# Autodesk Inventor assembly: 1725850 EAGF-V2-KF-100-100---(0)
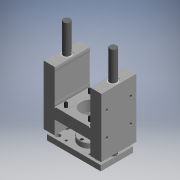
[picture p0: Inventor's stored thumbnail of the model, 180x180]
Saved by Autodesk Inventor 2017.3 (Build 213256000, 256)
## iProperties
Category: PARTsolutions
Company: FESTO
Part Number: 1725850 EAGF-V2-KF-100-100---(0)
Catalog Web Link: www.cadenas.de
Description: EAGF-guide unit
Vendor: FESTO
Document SubType Name: Assembly
Designer: partserver
Manufacturer: FESTO
Mass: 14023 g
Surface Area: 4822.3 cm^2
Volume: 3416.6 cm^3
Density: 4.10438 g/cm^3
Title: 1725850 EAGF-V2-KF-100-100
Author: Cadenas PARTsolutions
Comments: guide unit
PSOL_IDENT_0: {ATYP=ASSISTANT},{DATA=script=$CADENAS_DATA/23d-libs/festo/webfesto.vbb&M_FAMILY=EAGF&M_GROUP=01&M_P
PSOL_IDENT_1: ARTNO=1725850&IDCODE1=EAGF-V2-KF-100-100&IDCODE2=&customer_number_cns=&MATES=1&LOD=HI&LOCKERP=0&SING
PSOL_IDENT_2: LEPART=1}
NB: 1725850 EAGF-V2-KF-100-100---(0)
NN: EAGF
NT: guide unit
NBSYN: $TNR. $TYP.---($HUBST.)
LINA: 1725850 EAGF-V2-KF-100-100
CATALOG: Festo
TNR: 1725850
TYP: EAGF-V2-KF-100-100
HUBST: 0
L1: 362.8
L2: 126.6
L3: 220
L4: 40
L5: 128
L6: 20
L7: 24.5
L8: 89
L9: 0
L10: 15
L11: 39
H1: 213
H2: 200
H3: 89
H4: 150
H5: 131
H6: 172
H7: 150
B1: 130
B2: 120
B3: 89
B4: 89
B5: 89
D1: 87
D2: 25
D3: 18
D4: 11
D5: 70
KK: M20x1.5
G1: M18
G2: M10
G3: M10
T1: 20
T2: 11
SW: 27
CNSMASSEXACT: 14.023
SUPPLIER: FESTO
ARTICLENO: 1725850 EAGF-V2-KF-100-100---(0)
BOMINFO: 1725850 EAGF-V2-KF-100-100
CREATOR: CADENAS GmbH
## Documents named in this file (12)
- e:\temp\worker_18\temp\exporttempdir_1120_80_rasIC\format_0\1725850 EAGF-V2-KF-100-100---(0).iam
- e:\temp\worker_18\temp\exporttempdir_1120_80_rasIC\format_0\2608532 EAGF-V2-KF-100---(F).ipt
- e:\temp\worker_18\temp\exporttempdir_1120_80_rasIC\format_0\247465 FEN-80-SD---(SD).ipt
- e:\temp\worker_18\temp\exporttempdir_1120_80_rasIC\format_0\242770 EAGF 25x35x40---(B).ipt
- e:\temp\worker_18\temp\exporttempdir_1120_80_rasIC\format_0\1558863 EAGF-V2-KF-100---(J).ipt
- e:\temp\worker_18\temp\exporttempdir_1120_80_rasIC\format_0\1559396 EAGF-V2-KF-100---(R).ipt
- e:\temp\worker_18\temp\exporttempdir_1120_80_rasIC\format_0\1559400 EAGF-V2-KF-80_100---(GS).ipt
- e:\temp\worker_18\temp\exporttempdir_1120_80_rasIC\format_0\DIN-913 - M18x20.ipt
- e:\temp\worker_18\temp\exporttempdir_1120_80_rasIC\format_0\2608532 EAGF-100-100-KF---(FST).ipt
- e:\temp\worker_18\temp\exporttempdir_1120_80_rasIC\format_0\DIN-912 - M12x25(F).ipt
- e:\temp\worker_18\temp\exporttempdir_1120_80_rasIC\format_0\DIN-6912 - M12x25(F).ipt
- e:\temp\worker_18\temp\exporttempdir_1120_80_rasIC\format_0\DIN-912 - M10x50(F).ipt
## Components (25 placed, 11 different names)
1. 2608532 EAGF-V2-KF-100---(F):1 — ABSTREIF_V_1_XY@1 <-> ANBAU_XY@2, ABSTREIF_V_1_Z@1 <-> ANBAU_Z@2, ABSTREIF_V_1_YZ@1 <-> ANBAU_YZ@2, ABSTREIF_V_2_XY@1 <-> ANBAU_XY@3, ABSTREIF_V_2_Z@1 <-> ANBAU_Z@3, ABSTREIF_V_2_YZ@1 <-> ANBAU_YZ@3, BUSH_V_1_XY@1 <-> ANBAU_XY@4, BUSH_V_1_Z@1 <-> ANBAU_Z@4, BUSH_V_1_YZ@1 <-> ANBAU_YZ@4, BUSH_V_2_XY@1 <-> ANBAU_XY@5, BUSH_V_2_Z@1 <-> ANBAU_Z@5, BUSH_V_2_YZ@1 <-> ANBAU_YZ@5, ABSTREIF_H_1_XY@1 <-> ANBAU_XY@6, ABSTREIF_H_1_Z@1 <-> ANBAU_Z@6, ABSTREIF_H_1_YZ@1 <-> ANBAU_YZ@6, ABSTREIF_H_2_XY@1 <-> ANBAU_XY@7, ABSTREIF_H_2_Z@1 <-> ANBAU_Z@7, ABSTREIF_H_2_YZ@1 <-> ANBAU_YZ@7, BUSH_H_1_XY@1 <-> ANBAU_XY@8, BUSH_H_1_Z@1 <-> ANBAU_Z@8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
2. 247465 FEN-80-SD---(SD):1 — ABSTREIF_V_1_XY@1 <-> ANBAU_XY@2, ABSTREIF_V_1_Z@1 <-> ANBAU_Z@2, ABSTREIF_V_1_YZ@1 <-> ANBAU_YZ@2
3. 247465 FEN-80-SD---(SD):2 — ABSTREIF_V_2_XY@1 <-> ANBAU_XY@3, ABSTREIF_V_2_Z@1 <-> ANBAU_Z@3, ABSTREIF_V_2_YZ@1 <-> ANBAU_YZ@3
4. 242770 EAGF 25x35x40---(B):1 — BUSH_V_1_XY@1 <-> ANBAU_XY@4, BUSH_V_1_Z@1 <-> ANBAU_Z@4, BUSH_V_1_YZ@1 <-> ANBAU_YZ@4
5. 242770 EAGF 25x35x40---(B):2 — BUSH_V_2_XY@1 <-> ANBAU_XY@5, BUSH_V_2_Z@1 <-> ANBAU_Z@5, BUSH_V_2_YZ@1 <-> ANBAU_YZ@5
6. 247465 FEN-80-SD---(SD):3 — ABSTREIF_H_1_XY@1 <-> ANBAU_XY@6, ABSTREIF_H_1_Z@1 <-> ANBAU_Z@6, ABSTREIF_H_1_YZ@1 <-> ANBAU_YZ@6
7. 247465 FEN-80-SD---(SD):4 — ABSTREIF_H_2_XY@1 <-> ANBAU_XY@7, ABSTREIF_H_2_Z@1 <-> ANBAU_Z@7, ABSTREIF_H_2_YZ@1 <-> ANBAU_YZ@7
8. 242770 EAGF 25x35x40---(B):3 — BUSH_H_1_XY@1 <-> ANBAU_XY@8, BUSH_H_1_Z@1 <-> ANBAU_Z@8, BUSH_H_1_YZ@1 <-> ANBAU_YZ@8
9. 242770 EAGF 25x35x40---(B):4 — BUSH_H_2_XY@1 <-> ANBAU_XY@9, BUSH_H_2_Z@1 <-> ANBAU_Z@9, BUSH_H_2_YZ@1 <-> ANBAU_YZ@9
10. 1558863 EAGF-V2-KF-100---(J):1 — JOCH_Z@1 <-> ANBAU_Z@10, JOCH_YZ@1 <-> ANBAU_YZ@10, RING_XY@10 <-> ANBAU_XY@11, RING_Z@10 <-> ANBAU_Z@11, RING_YZ@10 <-> ANBAU_YZ@11, STANGE_XY@10 <-> ANBAU_XY@14, STANGE_Z@10 <-> ANBAU_Z@14, STANGE_2_XY@10 <-> ANBAU_XY@15, STANGE_2_Z@10 <-> ANBAU_Z@15, SCREW_1_XY@10 <-> ANBAU_XY@16, SCREW_1_Z@10 <-> ANBAU_Z@16, SCREW_1_YZ@10 <-> ANBAU_YZ@16, SCREW_2_XY@10 <-> ANBAU_XY@17, SCREW_2_Z@10 <-> ANBAU_Z@17, SCREW_2_YZ@10 <-> ANBAU_YZ@17, SCREW_3_XY@10 <-> ANBAU_XY@18, SCREW_3_Z@10 <-> ANBAU_Z@18, SCREW_3_YZ@10 <-> ANBAU_YZ@18, SCREW_4_XY@10 <-> ANBAU_XY@19, SCREW_4_Z@10 <-> ANBAU_Z@19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
11. 1559396 EAGF-V2-KF-100---(R):1 — RING_XY@10 <-> ANBAU_XY@11, RING_Z@10 <-> ANBAU_Z@11, RING_YZ@10 <-> ANBAU_YZ@11, EP_IP_XY@11 <-> ANBAU_XY@12, EP_IP_Z@11 <-> ANBAU_Z@12, EP_IP_YZ@11 <-> ANBAU_YZ@12
12. 1559400 EAGF-V2-KF-80_100---(GS):1 — EP_IP_XY@11 <-> ANBAU_XY@12, EP_IP_Z@11 <-> ANBAU_Z@12, EP_IP_YZ@11 <-> ANBAU_YZ@12, EP_IP_Z@12 <-> IP2_Z@13
13. DIN-913 - M18x20:1 — EP_IP_Z@12 <-> IP2_Z@13
14. 2608532 EAGF-100-100-KF---(FST):1 — STANGE_XY@10 <-> ANBAU_XY@14, STANGE_Z@10 <-> ANBAU_Z@14
15. 2608532 EAGF-100-100-KF---(FST):2 — STANGE_2_XY@10 <-> ANBAU_XY@15, STANGE_2_Z@10 <-> ANBAU_Z@15
16. DIN-912 - M12x25(F):1 — SCREW_1_XY@10 <-> ANBAU_XY@16, SCREW_1_Z@10 <-> ANBAU_Z@16, SCREW_1_YZ@10 <-> ANBAU_YZ@16
17. DIN-912 - M12x25(F):2 — SCREW_2_XY@10 <-> ANBAU_XY@17, SCREW_2_Z@10 <-> ANBAU_Z@17, SCREW_2_YZ@10 <-> ANBAU_YZ@17
18. DIN-912 - M12x25(F):3 — SCREW_3_XY@10 <-> ANBAU_XY@18, SCREW_3_Z@10 <-> ANBAU_Z@18, SCREW_3_YZ@10 <-> ANBAU_YZ@18
19. DIN-912 - M12x25(F):4 — SCREW_4_XY@10 <-> ANBAU_XY@19, SCREW_4_Z@10 <-> ANBAU_Z@19, SCREW_4_YZ@10 <-> ANBAU_YZ@19
20. DIN-6912 - M12x25(F):1 — DIN6912_1_XY@10 <-> MONTAGE_XY@20, DIN6912_1_Z@10 <-> MONTAGE_Z@20
21. DIN-6912 - M12x25(F):2 — DIN6912_2_XY@10 <-> MONTAGE_XY@21, DIN6912_2_Z@10 <-> MONTAGE_Z@21
22. DIN-912 - M10x50(F):1
23. DIN-912 - M10x50(F):2
24. DIN-912 - M10x50(F):3
25. DIN-912 - M10x50(F):4
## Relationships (57: Mate 36, Angle 15, Flush 6)
- ABSTREIF_V_1_XY@1 <-> ANBAU_XY@2 [Mate]: 2608532 EAGF-V2-KF-100---(F):1 ↔ 247465 FEN-80-SD---(SD):1
- ABSTREIF_V_1_Z@1 <-> ANBAU_Z@2 [Mate]: 2608532 EAGF-V2-KF-100---(F):1 ↔ 247465 FEN-80-SD---(SD):1
- ABSTREIF_V_1_YZ@1 <-> ANBAU_YZ@2 [Angle]: 2608532 EAGF-V2-KF-100---(F):1 ↔ 247465 FEN-80-SD---(SD):1
- ABSTREIF_V_2_XY@1 <-> ANBAU_XY@3 [Mate]: 2608532 EAGF-V2-KF-100---(F):1 ↔ 247465 FEN-80-SD---(SD):2
- ABSTREIF_V_2_Z@1 <-> ANBAU_Z@3 [Mate]: 2608532 EAGF-V2-KF-100---(F):1 ↔ 247465 FEN-80-SD---(SD):2
- ABSTREIF_V_2_YZ@1 <-> ANBAU_YZ@3 [Angle]: 2608532 EAGF-V2-KF-100---(F):1 ↔ 247465 FEN-80-SD---(SD):2
- BUSH_V_1_XY@1 <-> ANBAU_XY@4 [Mate]: 2608532 EAGF-V2-KF-100---(F):1 ↔ 242770 EAGF 25x35x40---(B):1
- BUSH_V_1_Z@1 <-> ANBAU_Z@4 [Mate]: 2608532 EAGF-V2-KF-100---(F):1 ↔ 242770 EAGF 25x35x40---(B):1
- BUSH_V_1_YZ@1 <-> ANBAU_YZ@4 [Angle]: 2608532 EAGF-V2-KF-100---(F):1 ↔ 242770 EAGF 25x35x40---(B):1
- BUSH_V_2_XY@1 <-> ANBAU_XY@5 [Mate]: 2608532 EAGF-V2-KF-100---(F):1 ↔ 242770 EAGF 25x35x40---(B):2
- BUSH_V_2_Z@1 <-> ANBAU_Z@5 [Mate]: 2608532 EAGF-V2-KF-100---(F):1 ↔ 242770 EAGF 25x35x40---(B):2
- BUSH_V_2_YZ@1 <-> ANBAU_YZ@5 [Angle]: 2608532 EAGF-V2-KF-100---(F):1 ↔ 242770 EAGF 25x35x40---(B):2
- ABSTREIF_H_1_XY@1 <-> ANBAU_XY@6 [Mate]: 2608532 EAGF-V2-KF-100---(F):1 ↔ 247465 FEN-80-SD---(SD):3
- ABSTREIF_H_1_Z@1 <-> ANBAU_Z@6 [Mate]: 2608532 EAGF-V2-KF-100---(F):1 ↔ 247465 FEN-80-SD---(SD):3
- ABSTREIF_H_1_YZ@1 <-> ANBAU_YZ@6 [Angle]: 2608532 EAGF-V2-KF-100---(F):1 ↔ 247465 FEN-80-SD---(SD):3
- ABSTREIF_H_2_XY@1 <-> ANBAU_XY@7 [Mate]: 2608532 EAGF-V2-KF-100---(F):1 ↔ 247465 FEN-80-SD---(SD):4
- ABSTREIF_H_2_Z@1 <-> ANBAU_Z@7 [Mate]: 2608532 EAGF-V2-KF-100---(F):1 ↔ 247465 FEN-80-SD---(SD):4
- ABSTREIF_H_2_YZ@1 <-> ANBAU_YZ@7 [Angle]: 2608532 EAGF-V2-KF-100---(F):1 ↔ 247465 FEN-80-SD---(SD):4
- BUSH_H_1_XY@1 <-> ANBAU_XY@8 [Mate]: 2608532 EAGF-V2-KF-100---(F):1 ↔ 242770 EAGF 25x35x40---(B):3
- BUSH_H_1_Z@1 <-> ANBAU_Z@8 [Mate]: 2608532 EAGF-V2-KF-100---(F):1 ↔ 242770 EAGF 25x35x40---(B):3
- BUSH_H_1_YZ@1 <-> ANBAU_YZ@8 [Angle]: 2608532 EAGF-V2-KF-100---(F):1 ↔ 242770 EAGF 25x35x40---(B):3
- BUSH_H_2_XY@1 <-> ANBAU_XY@9 [Mate]: 2608532 EAGF-V2-KF-100---(F):1 ↔ 242770 EAGF 25x35x40---(B):4
- BUSH_H_2_Z@1 <-> ANBAU_Z@9 [Mate]: 2608532 EAGF-V2-KF-100---(F):1 ↔ 242770 EAGF 25x35x40---(B):4
- BUSH_H_2_YZ@1 <-> ANBAU_YZ@9 [Angle]: 2608532 EAGF-V2-KF-100---(F):1 ↔ 242770 EAGF 25x35x40---(B):4
- JOCH_Z@1 <-> ANBAU_Z@10 [Mate]: 2608532 EAGF-V2-KF-100---(F):1 ↔ 1558863 EAGF-V2-KF-100---(J):1
- JOCH_YZ@1 <-> ANBAU_YZ@10 [Angle]: 2608532 EAGF-V2-KF-100---(F):1 ↔ 1558863 EAGF-V2-KF-100---(J):1
- RING_XY@10 <-> ANBAU_XY@11 [Mate]: 1558863 EAGF-V2-KF-100---(J):1 ↔ 1559396 EAGF-V2-KF-100---(R):1
- RING_Z@10 <-> ANBAU_Z@11 [Mate]: 1558863 EAGF-V2-KF-100---(J):1 ↔ 1559396 EAGF-V2-KF-100---(R):1
- RING_YZ@10 <-> ANBAU_YZ@11 [Angle]: 1558863 EAGF-V2-KF-100---(J):1 ↔ 1559396 EAGF-V2-KF-100---(R):1
- EP_IP_XY@11 <-> ANBAU_XY@12 [Mate]: 1559396 EAGF-V2-KF-100---(R):1 ↔ 1559400 EAGF-V2-KF-80_100---(GS):1
- EP_IP_Z@11 <-> ANBAU_Z@12 [Mate]: 1559396 EAGF-V2-KF-100---(R):1 ↔ 1559400 EAGF-V2-KF-80_100---(GS):1
- EP_IP_YZ@11 <-> ANBAU_YZ@12 [Angle]: 1559396 EAGF-V2-KF-100---(R):1 ↔ 1559400 EAGF-V2-KF-80_100---(GS):1
- EP_IP_Z@12 <-> IP2_Z@13 [Mate]: 1559400 EAGF-V2-KF-80_100---(GS):1 ↔ DIN-913 - M18x20:1
- STANGE_XY@10 <-> ANBAU_XY@14 [Mate]: 1558863 EAGF-V2-KF-100---(J):1 ↔ 2608532 EAGF-100-100-KF---(FST):1
- STANGE_Z@10 <-> ANBAU_Z@14 [Mate]: 1558863 EAGF-V2-KF-100---(J):1 ↔ 2608532 EAGF-100-100-KF---(FST):1
- STANGE_2_XY@10 <-> ANBAU_XY@15 [Mate]: 1558863 EAGF-V2-KF-100---(J):1 ↔ 2608532 EAGF-100-100-KF---(FST):2
- STANGE_2_Z@10 <-> ANBAU_Z@15 [Mate]: 1558863 EAGF-V2-KF-100---(J):1 ↔ 2608532 EAGF-100-100-KF---(FST):2
- SCREW_1_XY@10 <-> ANBAU_XY@16 [Flush]: 1558863 EAGF-V2-KF-100---(J):1 ↔ DIN-912 - M12x25(F):1
- SCREW_1_Z@10 <-> ANBAU_Z@16 [Mate]: 1558863 EAGF-V2-KF-100---(J):1 ↔ DIN-912 - M12x25(F):1
- SCREW_1_YZ@10 <-> ANBAU_YZ@16 [Angle]: 1558863 EAGF-V2-KF-100---(J):1 ↔ DIN-912 - M12x25(F):1
- SCREW_2_XY@10 <-> ANBAU_XY@17 [Flush]: 1558863 EAGF-V2-KF-100---(J):1 ↔ DIN-912 - M12x25(F):2
- SCREW_2_Z@10 <-> ANBAU_Z@17 [Mate]: 1558863 EAGF-V2-KF-100---(J):1 ↔ DIN-912 - M12x25(F):2
- SCREW_2_YZ@10 <-> ANBAU_YZ@17 [Angle]: 1558863 EAGF-V2-KF-100---(J):1 ↔ DIN-912 - M12x25(F):2
- SCREW_3_XY@10 <-> ANBAU_XY@18 [Flush]: 1558863 EAGF-V2-KF-100---(J):1 ↔ DIN-912 - M12x25(F):3
- SCREW_3_Z@10 <-> ANBAU_Z@18 [Mate]: 1558863 EAGF-V2-KF-100---(J):1 ↔ DIN-912 - M12x25(F):3
- SCREW_3_YZ@10 <-> ANBAU_YZ@18 [Angle]: 1558863 EAGF-V2-KF-100---(J):1 ↔ DIN-912 - M12x25(F):3
- SCREW_4_XY@10 <-> ANBAU_XY@19 [Flush]: 1558863 EAGF-V2-KF-100---(J):1 ↔ DIN-912 - M12x25(F):4
- SCREW_4_Z@10 <-> ANBAU_Z@19 [Mate]: 1558863 EAGF-V2-KF-100---(J):1 ↔ DIN-912 - M12x25(F):4
- SCREW_4_YZ@10 <-> ANBAU_YZ@19 [Angle]: 1558863 EAGF-V2-KF-100---(J):1 ↔ DIN-912 - M12x25(F):4
- DIN6912_1_XY@10 <-> MONTAGE_XY@20 [Flush]: 1558863 EAGF-V2-KF-100---(J):1 ↔ DIN-6912 - M12x25(F):1
- DIN6912_1_Z@10 <-> MONTAGE_Z@20 [Mate]: 1558863 EAGF-V2-KF-100---(J):1 ↔ DIN-6912 - M12x25(F):1
- DIN6912_2_XY@10 <-> MONTAGE_XY@21 [Flush]: 1558863 EAGF-V2-KF-100---(J):1 ↔ DIN-6912 - M12x25(F):2
- DIN6912_2_Z@10 <-> MONTAGE_Z@21 [Mate]: 1558863 EAGF-V2-KF-100---(J):1 ↔ DIN-6912 - M12x25(F):2
- DIN912_1_Z@1 <-> ANBAU_Z@22 [Mate]: 2608532 EAGF-V2-KF-100---(F):1
- DIN912_2_Z@1 <-> ANBAU_Z@23 [Mate]: 2608532 EAGF-V2-KF-100---(F):1
- DIN912_3_Z@1 <-> ANBAU_Z@24 [Mate]: 2608532 EAGF-V2-KF-100---(F):1
- DIN912_4_Z@1 <-> ANBAU_Z@25 [Mate]: 2608532 EAGF-V2-KF-100---(F):1
